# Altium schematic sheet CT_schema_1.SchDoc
size 329 x 463 mm
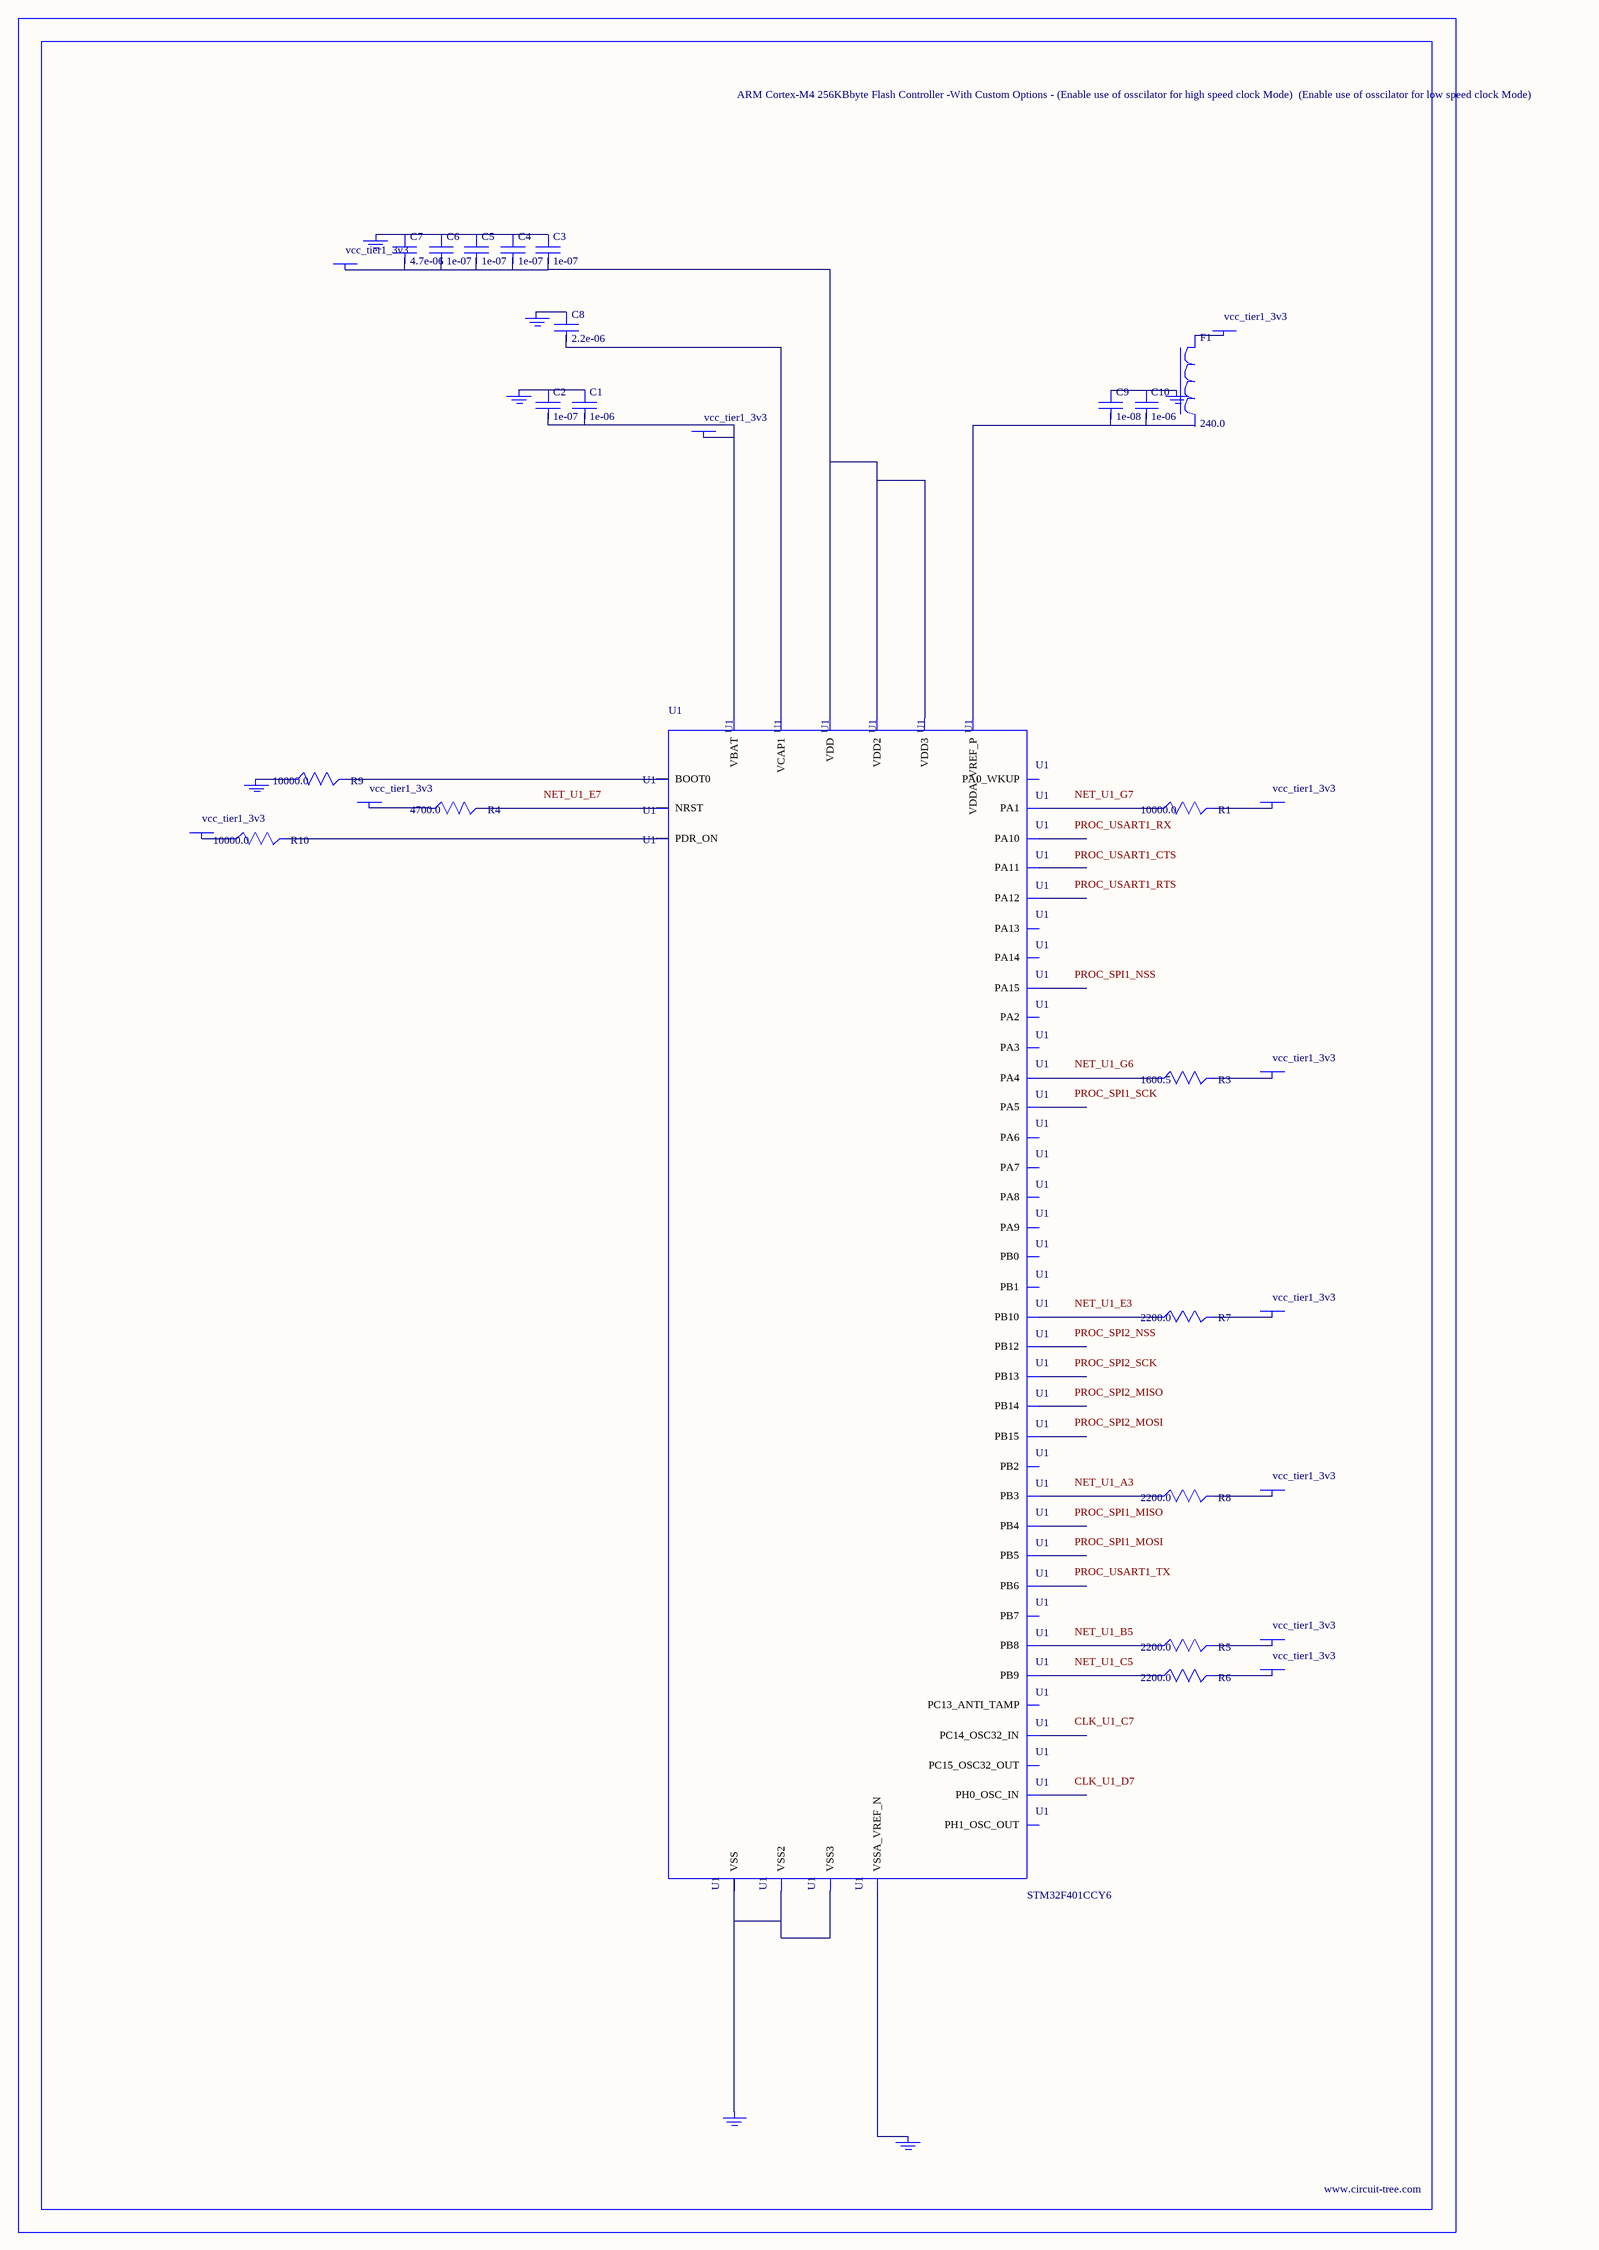
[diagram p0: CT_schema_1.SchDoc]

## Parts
BORDER0  (no value)
C1  1e-06  [C0603]
C2  1e-07  [C0603]
C3  1e-07  [C0603]
C4  1e-07  [C0603]
C5  1e-07  [C0603]
C6  1e-07  [C0603]
C7  4.7e-06  [C0603]
C8  2.2e-06  [C0603]
C9  1e-08  [C0603]
C10  1e-06  [C0603]
F1  240.0  [L0603]
GND_INSTANCE_0_0  (no value)
GND_INSTANCE_0_1  (no value)
GND_INSTANCE_0_2  (no value)
GND_INSTANCE_0_3  (no value)
GND_INSTANCE_0_4  (no value)
GND_INSTANCE_0_5  (no value)
GND_INSTANCE_0_6  (no value)
POWER_INSTANCE_0_0  vcc_tier1_3v3
POWER_INSTANCE_0_1  vcc_tier1_3v3
POWER_INSTANCE_0_2  vcc_tier1_3v3
POWER_INSTANCE_0_3  vcc_tier1_3v3
POWER_INSTANCE_0_4  vcc_tier1_3v3
POWER_INSTANCE_0_5  vcc_tier1_3v3
POWER_INSTANCE_0_6  vcc_tier1_3v3
POWER_INSTANCE_0_7  vcc_tier1_3v3
POWER_INSTANCE_0_8  vcc_tier1_3v3
POWER_INSTANCE_0_9  vcc_tier1_3v3
POWER_INSTANCE_0_10  vcc_tier1_3v3
R1  10000.0  [R0603]
R3  1600.5  [R0603]
R4  4700.0  [R0603]
R5  2200.0  [R0603]
R6  2200.0  [R0603]
R7  2200.0  [R0603]
R8  2200.0  [R0603]
R9  10000.0  [R0603]
R10  10000.0  [R0603]
U1  STM32F401CCY6  [WLCSP49]

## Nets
NetC1_1: C1.1 C2.1 GND_INSTANCE_0_0.0(GND)
NetC1_2: C1.2 C2.2 POWER_INSTANCE_0_0.0(PWR) U1.B7(VBAT)
NetC3_1: C3.1 C4.1 C5.1 C6.1 C7.1 GND_INSTANCE_0_2.0(GND)
NetC3_2: C3.2 C4.2 C5.2 C6.2 C7.2 POWER_INSTANCE_0_2.0(PWR) U1.A7(VDD) U1.B2(VDD2) U1.F2(VDD3)
NetC8_1: C8.1 GND_INSTANCE_0_4.0(GND)
NetC8_2: C8.2 U1.G2(VCAP1)
NetC9_1: C9.1 C10.1 GND_INSTANCE_0_1.0(GND)
NetC9_2: C9.2 C10.2 U1.F7(VDDA_VREF_P)
NetF1_1: F1.1 POWER_INSTANCE_0_1.0(PWR)
NetGND_INSTANCE_0_3_0: GND_INSTANCE_0_3.0(GND) R9.1
NetGND_INSTANCE_0_5_0: GND_INSTANCE_0_5.0(GND) U1.E6(VSSA_VREF_N)
NetGND_INSTANCE_0_6_0: GND_INSTANCE_0_6.0(GND) U1.A6(VSS) U1.B1(VSS2) U1.D3(VSS3)
NetPOWER_INSTANCE_0_3_0: POWER_INSTANCE_0_3.0(PWR) R10.1
NetPOWER_INSTANCE_0_4_0: POWER_INSTANCE_0_4.0(PWR) R4.1
NetPOWER_INSTANCE_0_5_0: POWER_INSTANCE_0_5.0(PWR) R1.2
NetPOWER_INSTANCE_0_6_0: POWER_INSTANCE_0_6.0(PWR) R3.2
NetPOWER_INSTANCE_0_7_0: POWER_INSTANCE_0_7.0(PWR) R7.2
NetPOWER_INSTANCE_0_8_0: POWER_INSTANCE_0_8.0(PWR) R8.2
NetPOWER_INSTANCE_0_9_0: POWER_INSTANCE_0_9.0(PWR) R5.2
NetPOWER_INSTANCE_0_10_0: POWER_INSTANCE_0_10.0(PWR) R6.2
NetR1_1: R1.1 U1.G7(PA1)
NetR3_1: R3.1 U1.G6(PA4)
NetR4_2: R4.2 U1.E7(NRST)
NetR5_1: R5.1 U1.B5(PB8)
NetR6_1: R6.1 U1.C5(PB9)
NetR7_1: R7.1 U1.E3(PB10)
NetR8_1: R8.1 U1.A3(PB3)
NetR9_2: R9.2 U1.A5(BOOT0)
NetR10_2: R10.2 U1.B6(PDR_ON)

Not connected (* = marked no-connect by the designer): F1 2; U1 A1(PA14) A2(PA15) A4(PB4) B3(PA13) B4(PB5) C1(PA11) C2(PA10) C3(PA12) C4(PB6) C6(PC15_OSC32_OUT) C7(PC14_OSC32_IN) D1(PA8) D2(PA9) D4(PB7) D5(PC13_ANTI_TAMP) D6(PH1_OSC_OUT) D7(PH0_OSC_IN) E1(PB15) E2(PB12) E4(PA3) E5(PA2) F1(PB14) F3(PA7) F4(PA6) F5(PA5) F6(PA0_WKUP) G1(PB13) G3(PB2) G4(PB1) G5(PB0)

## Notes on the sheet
- Labels drawn without touching a wire or pin: CLK_U1_C7, CLK_U1_D7, NET_U1_A3, NET_U1_B5, NET_U1_C5, NET_U1_E3, NET_U1_E7, NET_U1_G6, NET_U1_G7, PROC_SPI1_MISO, PROC_SPI1_MOSI, PROC_SPI1_NSS, PROC_SPI1_SCK, PROC_SPI2_MISO, PROC_SPI2_MOSI, PROC_SPI2_NSS, PROC_SPI2_SCK, PROC_USART1_CTS, PROC_USART1_RTS, PROC_USART1_RX, PROC_USART1_TX

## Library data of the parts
BORDER0 = BORDER_PAGE0
C1 C10 = C0603C105K3RACTU
C2-C6 = 06035C104K4Z2A
C7 = GRM188R6YA475KE15D
C8 = C0603C225K8RACTU
C9 = 06035C103K4Z2A
F1 = Z0603C241ASMST
GND_INSTANCE_0_0-GND_INSTANCE_0_6 = GND
POWER_INSTANCE_0_0-POWER_INSTANCE_0_10 = PWR
R1 R9 R10 = RC0603JR-0710KL
R3 = R3
R4 = RC0603JR-074K7L
R5-R8 = RC0603JR-072K2L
